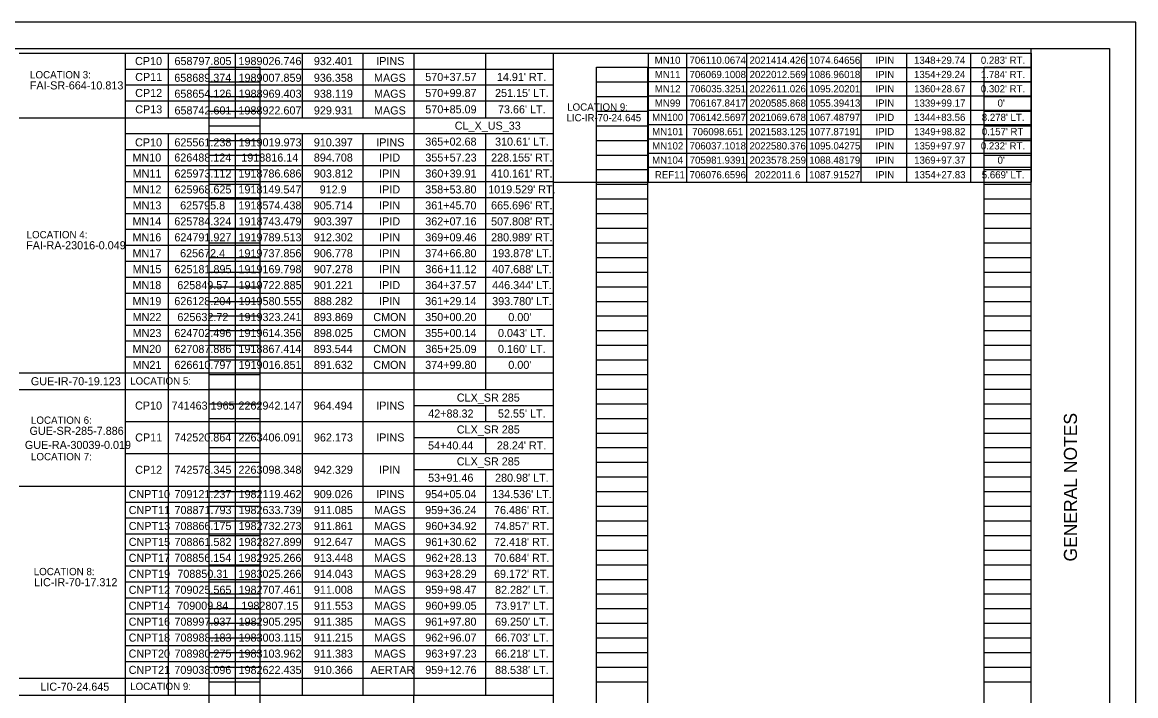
# Model space of a CAD drawing. Extents: x 0 to 34, y 0 to 22.
# Drawn here: x 12.68 to 34, y 9.11 to 22 of the extents above; entities that cross this region are included whole.
import ezdxf

# ---------------------------------------------------------------- set-up
doc = ezdxf.new("R2010")
doc.units = 0
for name, color, linetype in [('Default', 7, 'Continuous'), ('SH_Border', 7, 'Continuous'), ('SH_Cut_Line', 7, 'Continuous'), ('SH_Data', 7, 'Continuous'), ('SH_Text', 7, 'Continuous')]:
    doc.layers.add(name, color=color, linetype=linetype)

msp = doc.modelspace()

# ---------------------------------------------------------------- linework, layer by layer
at = {"layer": 'Default'}
for p, q in [((12.624, 21.411), (22.849, 21.411)), ((14.654, 21.411), (14.654, 9.126)), ((15.478, 21.411), (15.478, 20.174)), ((16.76, 21.411), (16.76, 20.174)), ((18.042, 21.411), (18.042, 20.174)), ((19.201, 21.411), (19.201, 20.174)), ((20.178, 21.411), (20.178, 9.126)), ((21.551, 21.411), (21.551, 20.174)), ((22.849, 21.411), (22.849, 9.126)), ((22.849, 21.411), (32, 21.411)), ((22.849, 21.411), (22.849, 18.938)), ((24.665, 21.411), (24.665, 18.938)), ((25.403, 21.411), (25.403, 18.938)), ((26.55, 21.411), (26.55, 18.938)), ((27.697, 21.411), (27.697, 18.938)), ((28.736, 21.411), (28.736, 18.938)), ((29.61, 21.411), (29.61, 18.938)), ((30.839, 21.411), (30.839, 18.938)), ((32, 21.411), (32, 18.938)), ((14.654, 21.105), (22.849, 21.105)), ((24.665, 21.137), (32, 21.137)), ((14.654, 20.8), (22.849, 20.8)), ((24.665, 20.864), (32, 20.864)), ((14.654, 20.495), (22.849, 20.495)), ((24.665, 20.591), (32, 20.591)), ((24.665, 20.318), (32, 20.318)), ((12.624, 20.174), (22.849, 20.174)), ((24.665, 20.045), (32, 20.045)), ((14.654, 19.869), (22.849, 19.869)), ((15.478, 19.869), (15.478, 9.126)), ((16.76, 19.869), (16.76, 9.126)), ((18.042, 19.869), (18.042, 9.126)), ((19.201, 19.869), (19.201, 9.126)), ((21.551, 19.869), (21.551, 14.971)), ((24.665, 19.771), (32, 19.771)), ((14.654, 19.564), (22.849, 19.564)), ((24.665, 19.498), (32, 19.498)), ((14.654, 19.259), (22.849, 19.259)), ((24.665, 19.225), (32, 19.225)), ((14.654, 18.954), (22.849, 18.954)), ((22.849, 18.938), (32, 18.938)), ((14.654, 18.648), (22.849, 18.648)), ((14.654, 18.343), (22.849, 18.343)), ((14.654, 18.038), (22.849, 18.038)), ((14.654, 17.733), (22.849, 17.733)), ((14.654, 17.428), (22.849, 17.428)), ((14.654, 17.122), (22.849, 17.122)), ((14.654, 16.817), (22.849, 16.817)), ((14.654, 16.512), (22.849, 16.512)), ((14.654, 16.207), (22.849, 16.207)), ((14.654, 15.902), (22.849, 15.902)), ((14.654, 15.596), (22.849, 15.596)), ((12.624, 15.291), (22.849, 15.291)), ((12.624, 14.971), (22.849, 14.971)), ((20.178, 14.666), (22.849, 14.666)), ((21.551, 14.666), (21.551, 14.36)), ((14.654, 14.36), (22.849, 14.36)), ((20.178, 14.055), (22.849, 14.055)), ((21.551, 14.055), (21.551, 13.75)), ((14.654, 13.75), (22.849, 13.75)), ((20.178, 13.445), (22.849, 13.445)), ((21.551, 13.445), (21.551, 9.126)), ((12.624, 13.124), (22.849, 13.124)), ((14.654, 12.819), (22.849, 12.819)), ((14.654, 12.514), (22.849, 12.514)), ((14.654, 12.209), (22.849, 12.209)), ((14.654, 11.903), (22.849, 11.903)), ((14.654, 11.598), (22.849, 11.598)), ((14.654, 11.293), (22.849, 11.293)), ((14.654, 10.988), (22.849, 10.988)), ((14.654, 10.683), (22.849, 10.683)), ((14.654, 10.377), (22.849, 10.377)), ((14.654, 10.072), (22.849, 10.072)), ((14.654, 9.767), (22.849, 9.767)), ((12.624, 9.447), (22.849, 9.447)), ((12.624, 9.126), (22.849, 9.126)), ((12.624, 9.126), (22.846, 9.126)), ((14.653, 9.126), (14.653, 0.826)), ((20.177, 9.126), (20.177, 0.826)), ((22.846, 9.126), (22.846, 0.826))]:
    msp.add_line(p, q, dxfattribs=at)
at = {"layer": 'SH_Border'}
msp.add_line((32, 0.5), (32, 21.5), dxfattribs=at)
msp.add_lwpolyline([(1.5, 21.5), (33.5, 21.5), (33.5, 0.5), (1.5, 0.5)], close=True, dxfattribs=at)
at = {"layer": 'SH_Cut_Line'}
msp.add_lwpolyline([(0, 0), (34, 0), (34, 22), (0, 22)], close=True, dxfattribs=at)
at = {"layer": 'SH_Data'}
for p, q in [((16.26, 0.98), (16.26, 21.14)), ((16.26, 21.14), (17.24, 21.14)), ((17.24, 0.98), (17.24, 21.14)), ((23.68, 0.98), (23.68, 21.14)), ((23.68, 21.14), (24.66, 21.14)), ((24.66, 0.98), (24.66, 21.14)), ((31.1, 0.98), (31.1, 21.14)), ((31.1, 21.14), (32, 21.14)), ((32, 0.98), (32, 21.14)), ((16.26, 20.86), (17.24, 20.86)), ((23.68, 20.86), (24.66, 20.86)), ((31.1, 20.86), (32, 20.86)), ((16.26, 20.58), (17.24, 20.58)), ((23.68, 20.58), (24.66, 20.58)), ((31.1, 20.58), (32, 20.58)), ((16.26, 20.3), (17.24, 20.3)), ((23.68, 20.3), (24.66, 20.3)), ((31.1, 20.3), (32, 20.3)), ((16.26, 20.02), (17.24, 20.02)), ((23.68, 20.02), (24.66, 20.02)), ((31.1, 20.02), (32, 20.02)), ((16.26, 19.74), (17.24, 19.74)), ((23.68, 19.74), (24.66, 19.74)), ((31.1, 19.74), (32, 19.74)), ((16.26, 19.46), (17.24, 19.46)), ((23.68, 19.46), (24.66, 19.46)), ((31.1, 19.46), (32, 19.46)), ((16.26, 19.18), (17.24, 19.18)), ((23.68, 19.18), (24.66, 19.18)), ((31.1, 19.18), (32, 19.18)), ((16.26, 18.9), (17.24, 18.9)), ((23.68, 18.9), (24.66, 18.9)), ((31.1, 18.9), (32, 18.9)), ((16.26, 18.62), (17.24, 18.62)), ((23.68, 18.62), (24.66, 18.62)), ((31.1, 18.62), (32, 18.62)), ((16.26, 18.34), (17.24, 18.34)), ((23.68, 18.34), (24.66, 18.34)), ((31.1, 18.34), (32, 18.34)), ((16.26, 18.06), (17.24, 18.06)), ((23.68, 18.06), (24.66, 18.06)), ((31.1, 18.06), (32, 18.06)), ((16.26, 17.78), (17.24, 17.78)), ((23.68, 17.78), (24.66, 17.78)), ((31.1, 17.78), (32, 17.78)), ((16.26, 17.5), (17.24, 17.5)), ((23.68, 17.5), (24.66, 17.5)), ((31.1, 17.5), (32, 17.5)), ((16.26, 17.22), (17.24, 17.22)), ((23.68, 17.22), (24.66, 17.22)), ((31.1, 17.22), (32, 17.22)), ((16.26, 16.94), (17.24, 16.94)), ((23.68, 16.94), (24.66, 16.94)), ((31.1, 16.94), (32, 16.94)), ((16.26, 16.66), (17.24, 16.66)), ((23.68, 16.66), (24.66, 16.66)), ((31.1, 16.66), (32, 16.66)), ((16.26, 16.38), (17.24, 16.38)), ((23.68, 16.38), (24.66, 16.38)), ((31.1, 16.38), (32, 16.38)), ((16.26, 16.1), (17.24, 16.1)), ((23.68, 16.1), (24.66, 16.1)), ((31.1, 16.1), (32, 16.1)), ((16.26, 15.82), (17.24, 15.82)), ((23.68, 15.82), (24.66, 15.82)), ((31.1, 15.82), (32, 15.82)), ((16.26, 15.54), (17.24, 15.54)), ((23.68, 15.54), (24.66, 15.54)), ((31.1, 15.54), (32, 15.54)), ((16.26, 15.26), (17.24, 15.26)), ((23.68, 15.26), (24.66, 15.26)), ((31.1, 15.26), (32, 15.26)), ((16.26, 14.98), (17.24, 14.98)), ((23.68, 14.98), (24.66, 14.98)), ((31.1, 14.98), (32, 14.98)), ((16.26, 14.7), (17.24, 14.7)), ((23.68, 14.7), (24.66, 14.7)), ((31.1, 14.7), (32, 14.7)), ((16.26, 14.42), (17.24, 14.42)), ((23.68, 14.42), (24.66, 14.42)), ((31.1, 14.42), (32, 14.42)), ((16.26, 14.14), (17.24, 14.14)), ((23.68, 14.14), (24.66, 14.14)), ((31.1, 14.14), (32, 14.14)), ((16.26, 13.86), (17.24, 13.86)), ((23.68, 13.86), (24.66, 13.86)), ((31.1, 13.86), (32, 13.86)), ((16.26, 13.58), (17.24, 13.58)), ((23.68, 13.58), (24.66, 13.58)), ((31.1, 13.58), (32, 13.58)), ((16.26, 13.3), (17.24, 13.3)), ((23.68, 13.3), (24.66, 13.3)), ((31.1, 13.3), (32, 13.3)), ((16.26, 13.02), (17.24, 13.02)), ((23.68, 13.02), (24.66, 13.02)), ((31.1, 13.02), (32, 13.02)), ((16.26, 12.74), (17.24, 12.74)), ((23.68, 12.74), (24.66, 12.74)), ((31.1, 12.74), (32, 12.74)), ((16.26, 12.46), (17.24, 12.46)), ((23.68, 12.46), (24.66, 12.46)), ((31.1, 12.46), (32, 12.46)), ((16.26, 12.18), (17.24, 12.18)), ((23.68, 12.18), (24.66, 12.18)), ((31.1, 12.18), (32, 12.18)), ((16.26, 11.9), (17.24, 11.9)), ((23.68, 11.9), (24.66, 11.9)), ((31.1, 11.9), (32, 11.9)), ((16.26, 11.62), (17.24, 11.62)), ((23.68, 11.62), (24.66, 11.62)), ((31.1, 11.62), (32, 11.62)), ((16.26, 11.34), (17.24, 11.34)), ((23.68, 11.34), (24.66, 11.34)), ((31.1, 11.34), (32, 11.34)), ((16.26, 11.06), (17.24, 11.06)), ((23.68, 11.06), (24.66, 11.06)), ((31.1, 11.06), (32, 11.06)), ((16.26, 10.78), (17.24, 10.78)), ((23.68, 10.78), (24.66, 10.78)), ((31.1, 10.78), (32, 10.78)), ((16.26, 10.5), (17.24, 10.5)), ((23.68, 10.5), (24.66, 10.5)), ((31.1, 10.5), (32, 10.5)), ((16.26, 10.22), (17.24, 10.22)), ((23.68, 10.22), (24.66, 10.22)), ((31.1, 10.22), (32, 10.22)), ((16.26, 9.94), (17.24, 9.94)), ((23.68, 9.94), (24.66, 9.94)), ((31.1, 9.94), (32, 9.94)), ((16.26, 9.66), (17.24, 9.66)), ((23.68, 9.66), (24.66, 9.66)), ((31.1, 9.66), (32, 9.66)), ((16.26, 9.38), (17.24, 9.38)), ((23.68, 9.38), (24.66, 9.38)), ((31.1, 9.38), (32, 9.38))]:
    msp.add_line(p, q, dxfattribs=at)

# ---------------------------------------------------------------- texts
at = {"layer": 'Default'}
for s, height, p in [('CP10', 0.1544, (14.844, 21.181)), ('658797.805', 0.1544, (15.598, 21.181)), ('1989026.746', 0.15443, (16.823, 21.181)), ('932.401', 0.1544, (18.267, 21.181)), ('IPINS', 0.1544, (19.461, 21.181)), ('MN10', 0.1382, (24.791, 21.205)), ('706110.0674', 0.13823, (25.458, 21.205)), ('2021414.426', 0.13823, (26.606, 21.205)), ('1074.64656', 0.1382, (27.749, 21.205)), ('IPIN', 0.1382, (29.018, 21.205)), ('1348+29.74', 0.1382, (29.756, 21.205)), ("0.283' RT.", 0.1382, (31.035, 21.205)), ('CP11', 0.1544, (14.846, 20.876)), ('658689.374', 0.1544, (15.595, 20.861)), ('1989007.859', 0.15443, (16.824, 20.861)), ('936.358', 0.1544, (18.266, 20.861)), ('MAGS', 0.1544, (19.418, 20.861)), ('570+37.57', 0.1544, (20.399, 20.876)), ("14.91' RT.", 0.1544, (21.77, 20.876)), ('MN11', 0.1382, (24.793, 20.932)), ('706069.1008', 0.13823, (25.459, 20.932)), ('2022012.569', 0.13823, (26.608, 20.932)), ('1086.96018', 0.1382, (27.749, 20.932)), ('IPIN', 0.1382, (29.018, 20.932)), ('1354+29.24', 0.1382, (29.756, 20.932)), ("1.784' RT.", 0.1382, (31.035, 20.932)), ('FAI-SR-664-10.813', 0.15443, (12.829, 20.715)), ('CP12', 0.1544, (14.846, 20.57)), ('658654.126', 0.1544, (15.596, 20.556)), ('1988969.403', 0.15443, (16.825, 20.556)), ('938.119', 0.1544, (18.267, 20.556)), ('MAGS', 0.1544, (19.418, 20.556)), ('570+99.87', 0.1544, (20.399, 20.57)), ("251.15' LT.", 0.15443, (21.735, 20.57)), ('MN12', 0.1382, (24.793, 20.658)), ('706035.3251', 0.13823, (25.461, 20.658)), ('2022611.026', 0.13823, (26.606, 20.658)), ('1095.20201', 0.1382, (27.75, 20.658)), ('IPIN', 0.1382, (29.018, 20.658)), ('1360+28.67', 0.1382, (29.758, 20.658)), ("0.302' RT.", 0.1382, (31.035, 20.658)), ('MN99', 0.1382, (24.793, 20.385)), ('706167.8417', 0.13823, (25.46, 20.385)), ('2020585.868', 0.13823, (26.607, 20.385)), ('1055.39413', 0.1382, (27.751, 20.385)), ('IPIN', 0.1382, (29.018, 20.385)), ('1339+99.17', 0.1382, (29.758, 20.385)), ("0'", 0.1382, (31.355, 20.385)), ('CP13', 0.1544, (14.847, 20.257)), ('658742.601', 0.1544, (15.598, 20.236)), ('1988922.607', 0.15443, (16.823, 20.236)), ('929.931', 0.1544, (18.267, 20.236)), ('MAGS', 0.1544, (19.418, 20.236)), ('570+85.09', 0.1544, (20.4, 20.257)), ("73.66' LT.", 0.1544, (21.791, 20.257)), ('MN100', 0.1382, (24.741, 20.112)), ('706142.5697', 0.13823, (25.46, 20.112)), ('2021069.678', 0.13823, (26.607, 20.112)), ('1067.48797', 0.1382, (27.749, 20.112)), ('IPID', 0.1382, (29.017, 20.112)), ('1344+83.56', 0.1382, (29.757, 20.112)), ("8.278' LT.", 0.1382, (31.053, 20.112)), ('CL_X_US_33', 0.1544, (20.964, 19.945)), ('LIC-IR-70-24.645', 0.13823, (23.104, 20.105)), ('MN101', 0.1382, (24.743, 19.839)), ('706098.651', 0.1382, (25.51, 19.839)), ('2021583.125', 0.13823, (26.608, 19.839)), ('1077.87191', 0.1382, (27.75, 19.839)), ('IPID', 0.1382, (29.017, 19.839)), ('1349+98.82', 0.1382, (29.759, 19.839)), ("0.157' RT", 0.1382, (31.053, 19.839)), ('CP10', 0.1544, (14.844, 19.625)), ('625561.238', 0.1544, (15.597, 19.625)), ('1919019.973', 0.15443, (16.825, 19.625)), ('910.397', 0.1544, (18.266, 19.625)), ('IPINS', 0.1544, (19.461, 19.625)), ('365+02.68', 0.1544, (20.399, 19.639)), ("310.61' LT.", 0.15443, (21.735, 19.639)), ('MN102', 0.1382, (24.743, 19.566)), ('706037.1018', 0.13823, (25.459, 19.566)), ('2022580.376', 0.13823, (26.606, 19.566)), ('1095.04275', 0.1382, (27.751, 19.566)), ('IPIN', 0.1382, (29.018, 19.566)), ('1359+97.97', 0.1382, (29.758, 19.566)), ("0.232' RT.", 0.1382, (31.035, 19.566)), ('MN10', 0.1544, (14.794, 19.334)), ('626488.124', 0.1544, (15.595, 19.334)), ('1918816.14', 0.1544, (16.877, 19.334)), ('894.708', 0.1544, (18.266, 19.334)), ('IPID', 0.1544, (19.516, 19.334)), ('355+57.23', 0.1544, (20.401, 19.334)), ("228.155' RT.", 0.15443, (21.659, 19.334)), ('MN104', 0.1382, (24.741, 19.293)), ('705981.9391', 0.13823, (25.461, 19.293)), ('2023578.259', 0.13823, (26.608, 19.293)), ('1088.48179', 0.1382, (27.75, 19.293)), ('IPIN', 0.1382, (29.018, 19.293)), ('1369+97.37', 0.1382, (29.758, 19.293)), ("0'", 0.1382, (31.355, 19.293)), ('625973.112', 0.1544, (15.598, 19.029)), ('1918786.686', 0.15443, (16.823, 19.029)), ('903.812', 0.1544, (18.267, 19.029)), ('360+39.91', 0.1544, (20.4, 19.029)), ("410.161' RT.", 0.15443, (21.659, 19.029)), ('MN11', 0.1544, (14.797, 19.029)), ('IPIN', 0.1544, (19.516, 19.029)), ('REF11', 0.1382, (24.794, 19.013)), ('706076.6596', 0.13823, (25.459, 19.013)), ('2022011.6', 0.1382, (26.706, 19.013)), ('1087.91527', 0.1382, (27.749, 19.013)), ('IPIN', 0.1382, (29.018, 19.013)), ('1354+27.83', 0.1382, (29.76, 19.013)), ("5.669' LT.", 0.1382, (31.053, 19.013)), ('MN12', 0.1544, (14.797, 18.724)), ('625968.625', 0.1544, (15.598, 18.724)), ('1918149.547', 0.15443, (16.823, 18.724)), ('912.9', 0.1544, (18.378, 18.724)), ('IPID', 0.1544, (19.516, 18.724)), ('358+53.80', 0.1544, (20.398, 18.724)), ("1019.529' RT.", 0.15443, (21.604, 18.724)), ('MN13', 0.1544, (14.797, 18.419)), ('625795.8', 0.1544, (15.707, 18.419)), ('1918574.438', 0.15443, (16.823, 18.419)), ('905.714', 0.1544, (18.264, 18.419)), ('IPIN', 0.1544, (19.516, 18.419)), ('361+45.70', 0.1544, (20.398, 18.419)), ("665.696' RT.", 0.15443, (21.659, 18.419)), ('MN14', 0.1544, (14.794, 18.113)), ('625784.324', 0.1544, (15.595, 18.113)), ('1918743.479', 0.15443, (16.824, 18.113)), ('903.397', 0.1544, (18.266, 18.113)), ('IPID', 0.1544, (19.516, 18.113)), ('362+07.16', 0.1544, (20.399, 18.113)), ("507.808' RT.", 0.15443, (21.659, 18.113)), ('MN16', 0.1544, (14.795, 17.808)), ('624791.927', 0.1544, (15.597, 17.808)), ('1919789.513', 0.15443, (16.825, 17.808)), ('912.302', 0.1544, (18.267, 17.808)), ('IPIN', 0.1544, (19.516, 17.808)), ('369+09.46', 0.1544, (20.399, 17.808)), ("280.989' RT.", 0.15443, (21.659, 17.808)), ('FAI-RA-23016-0.049', 0.15443, (12.759, 17.656)), ('MN17', 0.1544, (14.796, 17.503)), ('625672.4', 0.1544, (15.706, 17.503)), ('1919737.856', 0.15443, (16.823, 17.503)), ('906.778', 0.1544, (18.266, 17.503)), ('IPIN', 0.1544, (19.516, 17.503)), ('374+66.80', 0.1544, (20.398, 17.503)), ("193.878' LT.", 0.15443, (21.68, 17.503)), ('MN15', 0.1544, (14.797, 17.198)), ('625181.895', 0.1544, (15.598, 17.198)), ('1919169.798', 0.15443, (16.823, 17.198)), ('907.278', 0.1544, (18.266, 17.198)), ('IPIN', 0.1544, (19.516, 17.198)), ('366+11.12', 0.1544, (20.4, 17.198)), ("407.688' LT.", 0.15443, (21.68, 17.198)), ('MN18', 0.1544, (14.795, 16.893)), ('625849.57', 0.1544, (15.652, 16.893)), ('1919722.885', 0.15443, (16.825, 16.893)), ('901.221', 0.1544, (18.267, 16.893)), ('IPID', 0.1544, (19.516, 16.893)), ('364+37.57', 0.1544, (20.399, 16.893)), ("446.344' LT.", 0.15443, (21.68, 16.893)), ('MN19', 0.1544, (14.796, 16.587)), ('626128.204', 0.1544, (15.595, 16.587)), ('1919580.555', 0.15443, (16.825, 16.587)), ('888.282', 0.1544, (18.267, 16.587)), ('IPIN', 0.1544, (19.516, 16.587)), ('361+29.14', 0.1544, (20.397, 16.587)), ("393.780' LT.", 0.15443, (21.68, 16.587)), ('MN22', 0.1544, (14.797, 16.282)), ('625632.72', 0.1544, (15.654, 16.282)), ('1919323.241', 0.15443, (16.824, 16.282)), ('893.869', 0.1544, (18.267, 16.282)), ('CMON', 0.1544, (19.404, 16.282)), ('350+00.20', 0.1544, (20.398, 16.282)), ("0.00'", 0.1544, (21.989, 16.282)), ('MN23', 0.1544, (14.797, 15.977)), ('624702.496', 0.1544, (15.596, 15.977)), ('1919614.356', 0.15443, (16.823, 15.977)), ('898.025', 0.1544, (18.267, 15.977)), ('CMON', 0.1544, (19.404, 15.977)), ('355+00.14', 0.1544, (20.397, 15.977)), ("0.043' LT.", 0.1544, (21.791, 15.977)), ('MN20', 0.1544, (14.794, 15.672)), ('627087.886', 0.1544, (15.596, 15.672)), ('1918867.414', 0.15443, (16.822, 15.672)), ('893.544', 0.1544, (18.264, 15.672)), ('CMON', 0.1544, (19.404, 15.672)), ('365+25.09', 0.1544, (20.4, 15.672)), ("0.160' LT.", 0.1544, (21.791, 15.672)), ('MN21', 0.1544, (14.797, 15.367)), ('626610.797', 0.1544, (15.597, 15.367)), ('1919016.851', 0.15443, (16.824, 15.367)), ('891.632', 0.1544, (18.267, 15.367)), ('CMON', 0.1544, (19.404, 15.367)), ('374+99.80', 0.1544, (20.398, 15.367)), ("0.00'", 0.1544, (21.989, 15.367)), ('GUE-IR-70-19.123', 0.15443, (12.849, 15.054)), ('CP10', 0.1544, (14.844, 14.588)), ('741463.1965', 0.15443, (15.543, 14.588)), ('2262942.147', 0.15443, (16.823, 14.588)), ('964.494', 0.1544, (18.264, 14.588)), ('IPINS', 0.1544, (19.461, 14.588)), ('CLX_SR 285', 0.1544, (21.003, 14.741)), ('42+88.32', 0.1544, (20.456, 14.436)), ("52.55' LT.", 0.1544, (21.791, 14.436)), ('CLX_SR 285', 0.1544, (21.003, 14.131)), ('GUE-SR-285-7.886', 0.15443, (12.824, 14.105)), ('CP11', 0.1544, (14.846, 13.978)), ('742520.864', 0.1544, (15.595, 13.978)), ('2263406.091', 0.15443, (16.824, 13.978)), ('962.173', 0.1544, (18.268, 13.978)), ('IPINS', 0.1544, (19.461, 13.978)), (' GUE-RA-30039-0.019', 0.15443, (12.677, 13.835)), ('54+40.44', 0.1544, (20.453, 13.825)), ("28.24' RT.", 0.1544, (21.77, 13.825)), ('CLX_SR 285', 0.1544, (21.003, 13.52)), ('CP12', 0.1544, (14.846, 13.36)), ('742578.345', 0.1544, (15.598, 13.36)), ('2263098.348', 0.15443, (16.823, 13.36)), ('942.329', 0.1544, (18.267, 13.36)), ('IPIN', 0.1544, (19.516, 13.36)), ('53+91.46', 0.1544, (20.454, 13.207)), ("280.98' LT.", 0.15443, (21.735, 13.207)), ('CNPT10', 0.1544, (14.72, 12.894)), ('709121.237', 0.1544, (15.597, 12.894)), ('1982119.462', 0.15443, (16.824, 12.894)), ('909.026', 0.1544, (18.265, 12.894)), ('IPINS', 0.1544, (19.461, 12.894)), ('954+05.04', 0.1544, (20.397, 12.894)), ("134.536' LT.", 0.15443, (21.68, 12.894)), ('CNPT11', 0.1544, (14.722, 12.589)), ('708871.793', 0.1544, (15.599, 12.589)), ('1982633.739', 0.15443, (16.824, 12.589)), ('911.085', 0.1544, (18.267, 12.589)), ('MAGS', 0.1544, (19.418, 12.589)), ('959+36.24', 0.1544, (20.397, 12.589)), ("76.486' RT.", 0.15443, (21.715, 12.589)), ('CNPT13', 0.1544, (14.723, 12.284)), ('708866.175', 0.1544, (15.598, 12.284)), ('1982732.273', 0.15443, (16.825, 12.284)), ('911.861', 0.1544, (18.267, 12.284)), ('MAGS', 0.1544, (19.418, 12.284)), ('960+34.92', 0.1544, (20.4, 12.284)), ("74.857' RT.", 0.15443, (21.715, 12.284)), ('CNPT15', 0.1544, (14.723, 11.979)), ('708861.582', 0.1544, (15.598, 11.979)), ('1982827.899', 0.15443, (16.824, 11.979)), ('912.647', 0.1544, (18.266, 11.979)), ('MAGS', 0.1544, (19.418, 11.979)), ('961+30.62', 0.1544, (20.4, 11.979)), ("72.418' RT.", 0.15443, (21.715, 11.979)), ('CNPT17', 0.1544, (14.721, 11.674)), ('708856.154', 0.1544, (15.595, 11.674)), ('1982925.266', 0.15443, (16.823, 11.674)), ('913.448', 0.1544, (18.266, 11.674)), ('MAGS', 0.1544, (19.418, 11.674)), ('962+28.13', 0.1544, (20.401, 11.674)), ("70.684' RT.", 0.15443, (21.715, 11.674)), ('CNPT19', 0.1544, (14.722, 11.368)), ('708850.31', 0.1544, (15.653, 11.368)), ('1983025.266', 0.15443, (16.823, 11.368)), ('914.043', 0.1544, (18.268, 11.368)), ('MAGS', 0.1544, (19.418, 11.368)), ('963+28.29', 0.1544, (20.4, 11.368)), ("69.172' RT.", 0.15443, (21.715, 11.368)), ('LIC-IR-70-17.312', 0.15443, (12.91, 11.208)), ('CNPT12', 0.1544, (14.722, 11.063)), ('709025.565', 0.1544, (15.598, 11.063)), ('1982707.461', 0.15443, (16.824, 11.063)), ('911.008', 0.1544, (18.266, 11.063)), ('MAGS', 0.1544, (19.418, 11.063)), ('959+98.47', 0.1544, (20.399, 11.063)), ("82.282' LT.", 0.15443, (21.735, 11.063)), ('CNPT14', 0.1544, (14.72, 10.758)), ('709009.84', 0.1544, (15.651, 10.758)), ('1982807.15', 0.1544, (16.88, 10.758)), ('911.553', 0.1544, (18.268, 10.758)), ('MAGS', 0.1544, (19.418, 10.758)), ('960+99.05', 0.1544, (20.401, 10.758)), ("73.917' LT.", 0.15443, (21.735, 10.758)), ('CNPT16', 0.1544, (14.721, 10.453)), ('708997.937', 0.1544, (15.597, 10.453)), ('1982905.295', 0.15443, (16.825, 10.453)), ('911.385', 0.1544, (18.267, 10.453)), ('MAGS', 0.1544, (19.418, 10.453)), ('961+97.80', 0.1544, (20.398, 10.453)), ("69.250' LT.", 0.15443, (21.735, 10.453)), ('CNPT18', 0.1544, (14.721, 10.148)), ('708988.183', 0.1544, (15.599, 10.148)), ('1983003.115', 0.15443, (16.825, 10.148)), ('911.215', 0.1544, (18.267, 10.148)), ('MAGS', 0.1544, (19.418, 10.148)), ('962+96.07', 0.1544, (20.399, 10.148)), ("66.703' LT.", 0.15443, (21.735, 10.148)), ('CNPT20', 0.1544, (14.72, 9.842)), ('708980.275', 0.1544, (15.598, 9.842)), ('1983103.962', 0.15443, (16.824, 9.842)), ('911.383', 0.1544, (18.268, 9.842)), ('MAGS', 0.1544, (19.418, 9.842)), ('963+97.23', 0.1544, (20.401, 9.842)), ("66.218' LT.", 0.15443, (21.735, 9.842)), ('CNPT21', 0.1544, (14.722, 9.53)), ('709038.096', 0.1544, (15.596, 9.53)), ('1982622.435', 0.15443, (16.825, 9.53)), ('910.366', 0.1544, (18.265, 9.53)), ('AERTAR', 0.1544, (19.351, 9.53)), ('959+12.76', 0.1544, (20.399, 9.53)), ("88.538' LT.", 0.15443, (21.735, 9.53)), ('LIC-70-24.645', 0.15443, (13.03, 9.209))]:
    msp.add_text(s, height=height, dxfattribs=at).set_placement(p)
at = {"layer": 'SH_Data'}
msp.add_text('GENERAL NOTES', height=0.25, rotation=90, dxfattribs=at).set_placement((32.875, 11.682))
at = {"layer": 'SH_Text'}
for s, p in [('LOCATION 3:', (12.833, 20.926)), ('LOCATION 9:', (23.115, 20.308)), ('LOCATION 4:', (12.767, 17.866)), ('LOCATION 5:', (14.75, 15.067)), ('LOCATION 6:', (12.85, 14.316)), ('LOCATION 7:', (12.851, 13.618)), ('LOCATION 8:', (12.904, 11.419)), ('LOCATION 9:', (14.75, 9.222))]:
    msp.add_text(s, height=0.14, dxfattribs=at).set_placement(p)

doc.saveas('drawing.dxf')
